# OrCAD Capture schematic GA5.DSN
size A
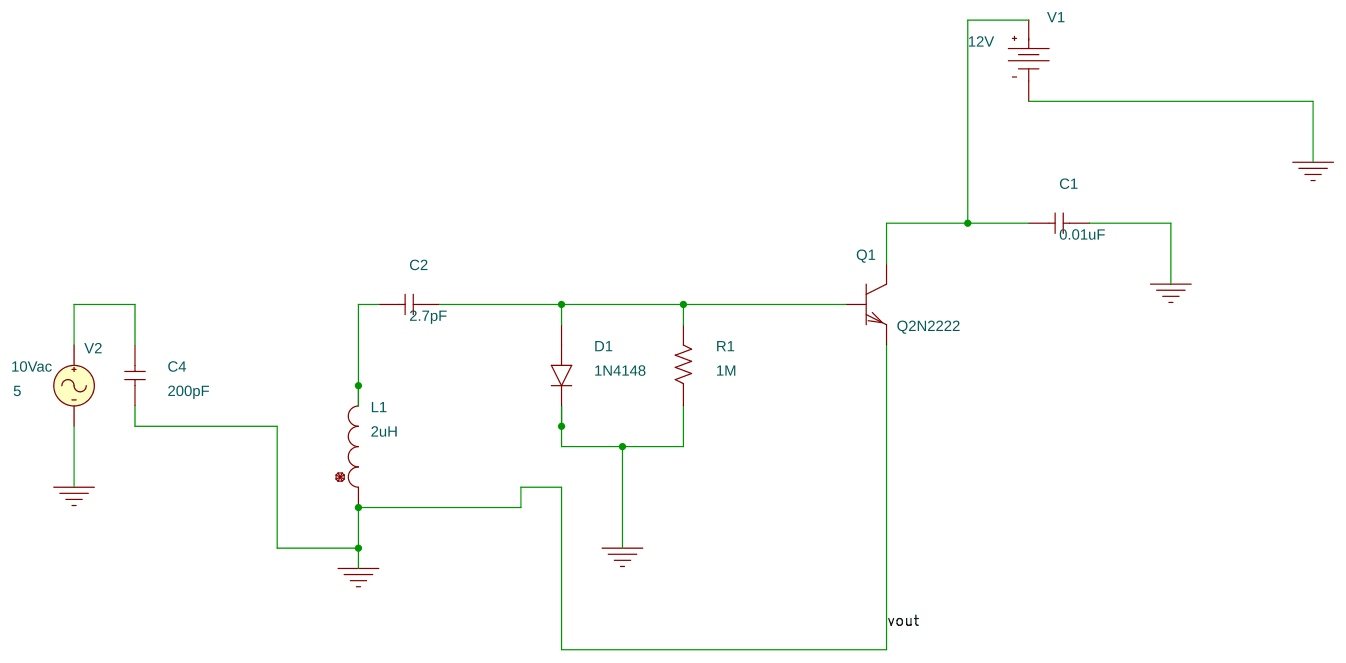
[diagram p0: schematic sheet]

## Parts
C1  0.01uF  [RAD/CK05]
C2  2.7pF  [RAD/CK05]
C4  200pF  [RAD/CK05]
D1  1N4148  [DO35]
L1  2uH  [DISC/.350x.175/LS.200x.100/.034]
Q1  Q2N2222  [TO18]
R1  1M  [AX/RC05]
V1  VDC
V2  VAC

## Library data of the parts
C1 C2 C4 = C
D1 = 1N4148
L1 = L_t
Q1 = Q2N2222
R1 = R
V1 = VDC: DC: 12V
V2 = VAC: ACMAG: 10Vac; DC: 5

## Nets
0: C1.2 C4.1 D1.1(CAT) L1.1 Q1.1(e) R1.1 V1.1(-) V2.2(-)
N00071: C1.1 Q1.3(c) V1.0(+)
N00248: C2.2 D1.2(AN) Q1.2(b) R1.2
N00445: C2.1 L1.2
N00493: C4.2 V2.1(+)
